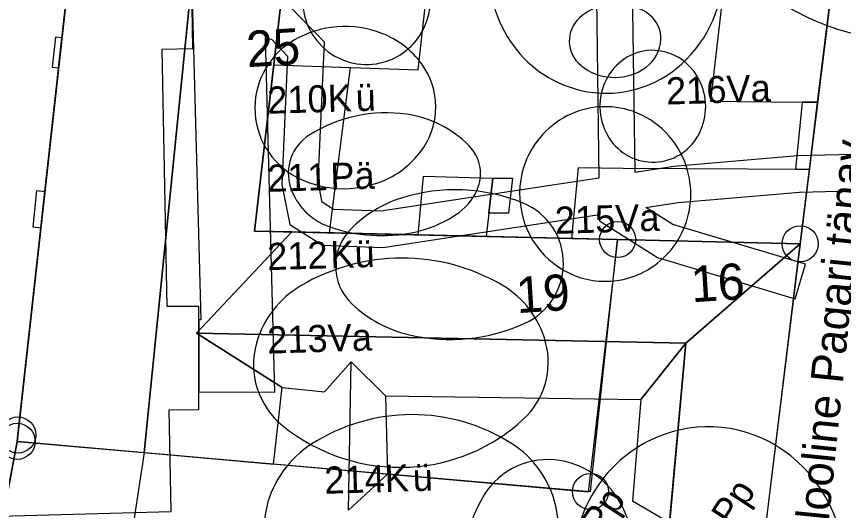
# Model space of a CAD drawing. Extents: x 738423 to 738903, y 6589762 to 6590172.
# Drawn here: x 738590.9 to 738636.72, y 6589894.31 to 6589921.66 of the extents above; entities that cross this region are included whole.
import ezdxf

# ---------------------------------------------------------------- set-up
doc = ezdxf.new("R2010")
doc.units = 0
for name, color, linetype in [('_1927_hoonestus', 7, 'Continuous'), ('_1927_katuse_kalded', 7, 'Continuous'), ('_1927_koordin_punktid_nr', 7, 'Continuous'), ('_1927_krundi_piir', 7, 'Continuous'), ('a_dendro_II_Vkl_puu', 7, 'Continuous'), ('a_dendro_III_vk_puu', 7, 'Continuous'), ('a_dendro_puu_nr', 7, 'Continuous'), ('a_dendro_V_vk_puu', 7, 'Continuous'), ('Default', 7, 'Continuous'), ('v_olol_hoone', 7, 'Continuous'), ('v_olol_kitsendus_tehnov', 7, 'Continuous'), ('v_vormistus_tekst', 7, 'Continuous')]:
    doc.layers.add(name, color=color, linetype=linetype)

# ---------------------------------------------------------------- blocks, each defined once
blk = doc.blocks.new('_U638')
at = {"layer": 'Default'}
for centre, radius, start, end in [((0.0017967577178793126, -0.006086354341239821), 0.016298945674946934, 62.43823725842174, 99.23130900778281), ((0.0017785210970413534, -0.00597414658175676), 0.01618526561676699, 99.23130900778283, 132.97828324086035), ((0.002383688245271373, -0.0049618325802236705), 0.015030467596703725, 24.06586474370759, 62.43823725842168), ((0.0009222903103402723, -0.005055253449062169), 0.014929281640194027, 132.97828324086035, 168.16056229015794), ((0.0028454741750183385, -0.004755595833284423), 0.014524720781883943, 325.34619089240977, 24.065864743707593), ((0.00048369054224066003, -0.004963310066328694), 0.0144811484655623, 168.16056229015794, 220.24997545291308), ((0.0015713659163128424, -0.003874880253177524), 0.016073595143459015, 269.78694623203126, 325.3461908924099), ((0.0015707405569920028, -0.004043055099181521), 0.01590541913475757, 220.24997545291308, 269.78694623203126)]:
    blk.add_arc(centre, radius, start, end, dxfattribs=at)
blk = doc.blocks.new('_U639')
at = {"layer": 'Default'}
for centre, radius, start, end in [((0.004641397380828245, -0.004188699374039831), 0.015204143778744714, 62.43823725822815, 111.04298782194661), ((0.003648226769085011, -0.001607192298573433), 0.01243817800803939, 111.04298782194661, 149.17299109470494), ((0.007830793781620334, 0.0019219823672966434), 0.008311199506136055, 354.7908139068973, 62.43823725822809), ((-0.0005217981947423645, 0.0008813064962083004), 0.007582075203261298, 149.1729910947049, 198.6357057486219), ((0.006724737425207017, 0.002022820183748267), 0.00942184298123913, 300.55754800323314, 354.7908139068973), ((0.0002487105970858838, 0.0011411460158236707), 0.008395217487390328, 198.63570574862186, 232.2443045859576), ((0.00306019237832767, 0.004771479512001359), 0.012986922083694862, 232.24430458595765, 259.1261887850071), ((0.0035614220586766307, 0.0073807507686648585), 0.015643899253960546, 259.1261887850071, 300.55754800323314)]:
    blk.add_arc(centre, radius, start, end, dxfattribs=at)
blk = doc.blocks.new('_U663')
at = {"layer": 'Default'}
for centre, radius, start, end in [((-0.003179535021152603, 0.002431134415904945), 0.009817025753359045, 76.98183598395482, 142.21769029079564), ((-0.00313893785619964, 0.0026067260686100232), 0.009636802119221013, 31.52910290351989, 76.98183598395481), ((-0.003567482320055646, 0.0027318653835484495), 0.009326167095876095, 142.2176902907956, 209.36902830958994), ((-0.0028356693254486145, 0.002792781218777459), 0.009281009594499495, 345.1635002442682, 31.529102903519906), ((-0.002983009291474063, 0.0028318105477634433), 0.009433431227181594, 318.45014178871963, 345.16350024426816), ((-0.0033842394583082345, 0.0028349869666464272), 0.009536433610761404, 209.36902830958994, 251.16622797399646), ((-0.003225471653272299, 0.00304669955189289), 0.00975741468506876, 292.19208800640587, 318.4501417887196), ((-0.0032726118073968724, 0.003162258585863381), 0.00988221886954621, 251.1662279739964, 292.1920880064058)]:
    blk.add_arc(centre, radius, start, end, dxfattribs=at)
blk = doc.blocks.new('_U672')
at = {"layer": 'Default'}
for centre, radius, start, end in [((-0.002101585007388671, 0.008719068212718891), 0.013254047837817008, 88.3470711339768, 146.6623908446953), ((-0.0021311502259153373, 0.007694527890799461), 0.014279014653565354, 39.22630250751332, 88.34707113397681), ((-0.01341153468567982, -0.0015141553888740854), 0.028840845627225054, 5.215032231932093, 39.22630250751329), ((0.010393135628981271, 0.000499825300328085), 0.02820978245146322, 146.6623908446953, 185.68101847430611), ((-0.013432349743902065, -0.0015160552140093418), 0.028861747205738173, 330.3262965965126, 5.215032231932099), ((0.010167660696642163, 0.0004773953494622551), 0.027983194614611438, 185.68101847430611, 223.49376727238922), ((-0.0006298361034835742, -0.008810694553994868), 0.014126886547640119, 279.58281790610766, 330.3262965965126), ((-0.0004907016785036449, -0.009634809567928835), 0.013291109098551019, 223.49376727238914, 279.5828179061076)]:
    blk.add_arc(centre, radius, start, end, dxfattribs=at)
blk = doc.blocks.new('_U666')
at = {"layer": 'Default'}
for centre, radius, start, end in [((0.00011899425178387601, -0.004345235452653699), 0.014377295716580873, 93.73643240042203, 132.97828326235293), ((0.00011601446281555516, -0.004299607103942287), 0.014331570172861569, 56.96948487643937, 93.73643240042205), ((0.0009683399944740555, -0.0029886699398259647), 0.012767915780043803, 17.930281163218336, 56.96948487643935), ((-0.0009846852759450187, -0.0031607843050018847), 0.012758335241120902, 132.9782832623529, 174.74476914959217), ((0.001317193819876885, -0.002875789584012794), 0.01240125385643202, 324.8404425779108, 17.930281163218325), ((-0.0013245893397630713, -0.0031295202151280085), 0.012416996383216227, 174.74476914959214, 226.8513130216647), ((-0.00011934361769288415, -0.0018639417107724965), 0.014158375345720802, 275.39216212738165, 324.8404425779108), ((-0.00012107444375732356, -0.001845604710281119), 0.014176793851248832, 226.85131302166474, 275.39216212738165)]:
    blk.add_arc(centre, radius, start, end, dxfattribs=at)
blk = doc.blocks.new('_U657')
at = {"layer": 'Default'}
for centre, radius, start, end in [((-0.00097990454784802, 0.0007999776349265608), 0.0072139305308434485, 87.51961632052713, 143.60493032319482), ((-0.000978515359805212, 0.0008320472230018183), 0.007181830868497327, 41.86952183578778, 87.51961632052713), ((-0.0008423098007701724, 0.0009541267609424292), 0.006998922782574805, 355.5925672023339, 41.869521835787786), ((-0.0011456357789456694, 0.00092214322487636), 0.007008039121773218, 143.60493032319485, 200.58225243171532), ((-0.0008819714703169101, 0.0009571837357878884), 0.00703870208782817, 318.4501417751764, 355.5925672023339), ((-0.00109799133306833, 0.0009400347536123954), 0.00705893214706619, 200.58225243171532, 241.43290441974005), ((-0.0010109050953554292, 0.001071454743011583), 0.007210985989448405, 281.7701057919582, 318.45014177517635), ((-0.001015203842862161, 0.0010920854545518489), 0.007232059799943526, 241.43290441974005, 281.7701057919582)]:
    blk.add_arc(centre, radius, start, end, dxfattribs=at)
blk = doc.blocks.new('_U658')
at = {"layer": 'Default'}
for centre, radius, start, end in [((-0.0005203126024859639, 0.00536265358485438), 0.008648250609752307, 93.96541354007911, 157.01522297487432), ((-0.0005176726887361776, 0.005324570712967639), 0.008686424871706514, 34.565999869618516, 93.96541354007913), ((-0.0026390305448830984, 0.0038630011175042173), 0.011262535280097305, 342.9805300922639, 34.56599986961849), ((0.0018660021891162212, 0.004350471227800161), 0.011240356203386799, 157.01522297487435, 211.61333323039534), ((-0.001366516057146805, 0.003473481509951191), 0.00993173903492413, 310.51471278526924, 342.9805300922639), ((0.0006726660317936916, 0.0036159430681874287), 0.009839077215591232, 211.61333323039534, 241.43290441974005), ((-0.00015588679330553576, 0.0020567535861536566), 0.008068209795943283, 274.37814596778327, 310.51471278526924), ((-0.00015839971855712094, 0.002089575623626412), 0.00810112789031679, 241.43290441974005, 274.3781459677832)]:
    blk.add_arc(centre, radius, start, end, dxfattribs=at)
blk = doc.blocks.new('_U659')
at = {"layer": 'Default'}
for centre, radius, start, end in [((0.0009135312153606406, 0.00814367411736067), 0.004993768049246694, 36.62143331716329, 112.83763452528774), ((0.001661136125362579, 0.006368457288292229), 0.006919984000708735, 112.83763452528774, 164.55428182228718), ((-0.007871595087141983, 0.0016141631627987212), 0.01593967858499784, 356.20504232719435, 36.621433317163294), ((0.011662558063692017, 0.0036050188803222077), 0.017296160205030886, 164.55428182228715, 196.5825048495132), ((-0.0041094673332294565, 0.0013646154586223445), 0.012169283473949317, 319.00795881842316, 356.2050423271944), ((0.007916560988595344, 0.0024895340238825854), 0.013387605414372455, 196.58250484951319, 219.71382654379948), ((0.0021317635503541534, -0.0023154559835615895), 0.005867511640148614, 219.71382654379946, 254.9708225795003), ((0.0017521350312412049, -0.003729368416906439), 0.004403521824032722, 254.97082257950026, 319.00795881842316)]:
    blk.add_arc(centre, radius, start, end, dxfattribs=at)
blk = doc.blocks.new('_U660')
at = {"layer": 'Default'}
for centre, radius, start, end in [((-0.00030942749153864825, 0.0014836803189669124), 0.0057334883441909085, 92.98118928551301, 140.95122577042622), ((-0.00030208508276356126, 0.0013426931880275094), 0.005874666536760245, 49.82920833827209, 92.98118928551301), ((-0.005270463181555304, -0.004542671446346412), 0.01357676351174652, 21.832289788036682, 49.829208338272), ((0.0060420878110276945, -0.003668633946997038), 0.013912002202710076, 140.95122577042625, 171.20520964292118), ((-0.011089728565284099, -0.006874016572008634), 0.019845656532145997, 342.07583257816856, 21.832289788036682), ((0.011936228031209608, -0.004580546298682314), 0.019876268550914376, 171.20520964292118, 208.92018104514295), ((0.0009415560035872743, -0.010765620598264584), 0.007200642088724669, 273.34239310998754, 342.0758325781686), ((0.00093529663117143, -0.010658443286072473), 0.007308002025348, 208.92018104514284, 273.3423931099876)]:
    blk.add_arc(centre, radius, start, end, dxfattribs=at)
blk = doc.blocks.new('_U661')
at = {"layer": 'Default'}
for centre, radius, start, end in [((-0.0030160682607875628, 0.007454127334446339), 0.008707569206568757, 78.4230499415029, 145.35801600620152), ((-0.003436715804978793, 0.005400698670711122), 0.010803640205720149, 34.65429433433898, 78.42304994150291), ((0.0068739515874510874, 0.000620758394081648), 0.02072869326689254, 145.35801600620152, 187.24173786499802), ((-0.012848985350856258, -0.001105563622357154), 0.022245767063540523, 4.5434303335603, 34.654294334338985), ((-0.01248887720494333, -0.001076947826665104), 0.021884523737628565, 333.96819896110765, 4.543430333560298), ((0.0062093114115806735, 0.0005363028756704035), 0.02005870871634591, 187.24173786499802, 226.85131301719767), ((-0.0021906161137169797, -0.00610682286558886), 0.010423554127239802, 289.0476065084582, 333.9681989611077), ((-0.0016057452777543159, -0.007800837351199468), 0.008631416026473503, 226.85131301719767, 289.0476065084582)]:
    blk.add_arc(centre, radius, start, end, dxfattribs=at)
blk = doc.blocks.new('_U662')
at = {"layer": 'Default'}
for centre, radius, start, end in [((-0.0028954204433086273, 0.006266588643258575), 0.009853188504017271, 80.49660816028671, 143.76371603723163), ((-0.0031717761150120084, 0.004615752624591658), 0.011526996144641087, 36.73116785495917, 80.49660816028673), ((0.0050267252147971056, 0.00046074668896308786), 0.019675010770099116, 143.76371603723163, 187.3383291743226), ((-0.0105701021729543, -0.0009050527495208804), 0.020758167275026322, 4.4809080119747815, 36.731167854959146), ((-0.010286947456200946, -0.0008828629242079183), 0.020474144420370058, 331.8756544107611, 4.48090801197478), ((0.00450953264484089, 0.0003941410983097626), 0.01915354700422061, 187.3383291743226, 228.46175316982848), ((-0.0021317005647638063, -0.0052418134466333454), 0.011227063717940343, 287.32246647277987, 331.8756544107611), ((-0.00170251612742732, -0.006617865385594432), 0.00978563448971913, 228.46175316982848, 287.32246647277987)]:
    blk.add_arc(centre, radius, start, end, dxfattribs=at)
blk = doc.blocks.new('_U665')
at = {"layer": 'Default'}
for centre, radius, start, end in [((-0.0029044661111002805, 0.0034915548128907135), 0.0034719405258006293, 46.56687312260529, 144.94764569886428), ((-0.004520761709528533, 0.0017843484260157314), 0.005822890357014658, 15.60075044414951, 46.56687312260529), ((-0.0008804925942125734, 0.0020715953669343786), 0.005944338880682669, 144.94764569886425, 215.63059108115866), ((-0.005270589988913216, 0.0015749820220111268), 0.00660139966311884, 346.56064947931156, 15.600750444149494), ((-0.004259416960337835, 0.0013333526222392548), 0.005561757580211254, 334.10172837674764, 346.56064947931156), ((-0.002239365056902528, 0.0010976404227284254), 0.004272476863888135, 215.63059108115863, 264.0891552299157), ((-0.003230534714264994, 0.0008337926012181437), 0.0044180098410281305, 320.11565064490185, 334.1017283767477), ((-0.002343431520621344, 9.247083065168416e-05), 0.0032619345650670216, 264.0891552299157, 320.11565064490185)]:
    blk.add_arc(centre, radius, start, end, dxfattribs=at)
blk = doc.blocks.new('_U664')
at = {"layer": 'Default'}
for centre, radius, start, end in [((-0.002498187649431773, -0.001611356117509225), 0.006568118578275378, 71.48372982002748, 126.93625442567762), ((-0.0023698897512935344, -0.001228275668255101), 0.006164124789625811, 41.982806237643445, 71.48372982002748), ((-0.0029878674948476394, -0.0009600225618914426), 0.005753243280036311, 126.93625442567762, 186.55361178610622), ((-0.0019370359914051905, -0.000838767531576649), 0.00558181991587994, 10.944438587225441, 41.98280623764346), ((-0.0018959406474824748, -0.0008308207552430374), 0.005539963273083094, 333.5917879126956, 10.944438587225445), ((-0.0030131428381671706, -0.000962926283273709), 0.0057278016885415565, 186.55361178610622, 244.4976123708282), ((-0.0024694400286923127, -0.0005460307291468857), 0.006180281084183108, 298.2944372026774, 333.5917879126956), ((-0.002652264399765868, -0.00020641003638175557), 0.006565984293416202, 244.49761237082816, 298.2944372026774)]:
    blk.add_arc(centre, radius, start, end, dxfattribs=at)

msp = doc.modelspace()

# ---------------------------------------------------------------- linework, layer by layer
at = {"layer": '_1927_hoonestus'}
for points in [[(738609.1419593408, 6589929.940140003), (738609.3368931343, 6589926.165239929), (738613.9533353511, 6589925.894244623), (738613.8912678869, 6589925.340685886), (738630.1483324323, 6589923.879602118), (738629.3435517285, 6589916.969136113), (738634.4211056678, 6589916.921415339), (738635.2838401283, 6589916.916987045), (738636.509191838, 6589926.891104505), (738627.5826462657, 6589928.059372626)], [(738605.5600914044, 6589922.532058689), (738605.1579677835, 6589918.9937799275), (738613.1474290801, 6589918.706638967), (738613.9533353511, 6589925.894244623), (738609.3368931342, 6589926.165239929), (738609.5082813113, 6589922.846301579), (738609.4744244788, 6589922.466374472)], [(738624.207189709, 6589909.313105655), (738622.5673353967, 6589895.324185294), (738590.9372064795, 6589898.135166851), (738593.6684053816, 6589922.731606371), (738605.5601169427, 6589922.53205826), (738605.1579677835, 6589918.9937799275), (738604.086427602, 6589909.782829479)], [(738593.4183435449, 6589920.479617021), (738593.0697797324, 6589920.519923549), (738592.878654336, 6589918.867104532), (738593.2337913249, 6589918.817589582)], [(738605.1579677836, 6589918.993779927), (738609.3886004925, 6589918.841731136), (738608.2173795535, 6589909.686391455), (738604.086427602, 6589909.782829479)], [(738634.4211056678, 6589916.921415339), (738634.0644192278, 6589913.2038506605), (738634.8273207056, 6589913.201010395), (738635.2838401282, 6589916.916987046)], [(738624.5146997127, 6589913.239404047), (738622.0179979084, 6589913.28052499), (738621.6553719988, 6589909.373207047), (738624.2071897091, 6589909.313105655), (738634.3211426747, 6589909.080822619), (738634.8273207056, 6589913.201010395)], [(738613.1604795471, 6589909.570993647), (738613.4556048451, 6589912.813731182), (738617.2915386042, 6589912.7055791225), (738616.9236948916, 6589909.483140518)], [(738617.2915386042, 6589912.7055791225), (738618.3765855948, 6589912.7055791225), (738618.1604766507, 6589910.776867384), (738617.0710209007, 6589910.7737674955)], [(738592.470753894, 6589911.945880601), (738592.0056230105, 6589912.0154890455), (738591.8046353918, 6589910.017250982), (738592.2500806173, 6589909.958556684)], [(738598.7561479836, 6589884.064893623), (738598.7561479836, 6589884.064893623), (738600.1654182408, 6589891.510843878), (738617.1576277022, 6589889.916511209), (738616.9587005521, 6589887.781161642), (738616.9587005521, 6589887.781161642), (738621.4793553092, 6589887.4869466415), (738621.2187353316, 6589884.178665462), (738631.1763472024, 6589883.225550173), (738634.3211426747, 6589909.080822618), (738624.2071897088, 6589909.313105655), (738622.5673353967, 6589895.324185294), (738590.9372064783, 6589898.13516685), (738590.9372064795, 6589898.13516685), (738586.1827055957, 6589872.62061175), (738613.3249623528, 6589869.722398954), (738613.2710881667, 6589869.728151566), (738614.3523733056, 6589877.812429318), (738614.3523733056, 6589877.812429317), (738614.3523733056, 6589877.812429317), (738615.0233334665, 6589882.235576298)]]:
    msp.add_lwpolyline(points, close=True, dxfattribs=at)
at = {"layer": '_1927_katuse_kalded'}
for points in [[(738597.9667878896, 6589897.510445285), (738600.5094751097, 6589922.616810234), (738593.6684053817, 6589922.73160637), (738590.9372064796, 6589898.13516685)], [(738597.9667878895, 6589897.510445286), (738605.1457848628, 6589896.872445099), (738605.6113334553, 6589901.124186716), (738600.881980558, 6589904.118928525), (738606.1519035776, 6589909.734610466), (738606.1519035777, 6589909.734610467), (738604.0864276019, 6589909.782829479), (738605.5600914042, 6589922.532058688), (738600.5094751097, 6589922.616810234)], [(738600.881980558, 6589904.118928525), (738627.9783805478, 6589903.577252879), (738634.3211426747, 6589909.080822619), (738606.1519035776, 6589909.734610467), (738606.1519035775, 6589909.734610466)], [(738634.3211545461, 6589909.080822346), (738627.9783805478, 6589903.577252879), (738626.1975412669, 6589883.702107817), (738631.1763472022, 6589883.225550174)], [(738600.881980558, 6589904.118928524), (738605.6113334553, 6589901.124186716), (738607.9681583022, 6589900.872549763), (738609.4494050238, 6589902.544400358), (738611.3403582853, 6589900.651739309), (738625.4909918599, 6589900.462473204), (738627.9783805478, 6589903.577252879)], [(738627.9783805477, 6589903.57725288), (738625.4909918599, 6589900.462473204), (738625.0359812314, 6589894.845607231), (738627.0879609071, 6589893.639680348)], [(738609.4494050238, 6589902.544400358), (738611.3403582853, 6589900.651739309), (738611.4495059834, 6589896.312231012), (738609.3012505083, 6589894.327721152)], [(738589.9993202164, 6589893.102093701), (738590.9372064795, 6589898.13516685), (738597.9667878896, 6589897.510445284), (738597.1362287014, 6589892.057225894), (738595.5346271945, 6589892.346110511)]]:
    msp.add_lwpolyline(points, close=True, dxfattribs=at)
at = {"layer": '_1927_koordin_punktid_nr'}
for centre in [(738624.2071897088, 6589909.313105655), (738634.3211426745, 6589909.080822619), (738590.9372064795, 6589898.13516685), (738590.975352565, 6589898.488217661), (738622.701350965, 6589895.352627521)]:
    msp.add_circle(centre, 0.9999999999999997, dxfattribs=at)
at = {"layer": '_1927_krundi_piir'}
for points in [[(738586.182705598, 6589872.620611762), (738590.9372064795, 6589898.13516685), (738590.975352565, 6589898.488217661), (738593.7110525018, 6589923.115674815), (738595.6482555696, 6589940.609766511), (738608.5799562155, 6589940.823351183), (738620.342268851, 6589941.795771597), (738638.2396178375, 6589940.94571321)], [(738638.2396178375, 6589940.94571321), (738636.5091918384, 6589926.8911045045), (738634.3211426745, 6589909.080822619), (738629.2817413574, 6589868.018556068)], [(738590.9372064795, 6589898.13516685), (738622.701350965, 6589895.352627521), (738624.2071897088, 6589909.313105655), (738634.3211426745, 6589909.080822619)]]:
    msp.add_lwpolyline(points, dxfattribs=at)
at = {"layer": 'v_olol_hoone'}
msp.add_lwpolyline([(738588.6389999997, 6589893.962), (738599.4669999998, 6589894.244), (738599.3599151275, 6589899.873880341), (738600.996, 6589899.9049999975), (738601.01, 6589905.608999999), (738599.250746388, 6589905.613317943), (738598.9797844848, 6589919.858869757), (738600.6690000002, 6589919.891000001), (738600.5770000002, 6589925.68), (738598.8695780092, 6589925.652865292), (738598.69, 6589935.093999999), (738587.8449999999, 6589934.8719999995), (738588.023237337, 6589925.688511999), (738587.4179999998, 6589925.677), (738587.4650000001, 6589923.205999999), (738588.0711907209, 6589923.217765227), (738588.4110435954, 6589905.707209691), (738587.885, 6589905.696999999), (738587.9331245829, 6589903.217432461), (738588.4591681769, 6589903.227642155)], close=True, dxfattribs=at)
at = {"layer": 'v_olol_kitsendus_tehnov'}
for points in [[(738645.6658428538, 6589914.234000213), (738634.174176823, 6589913.940901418), (738627.3268535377, 6589913.349518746), (738625.1699327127, 6589913.022275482), (738624.9687574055, 6589927.174521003)], [(738622.9712425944, 6589926.985478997), (738623.1740351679, 6589912.719462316), (738611.0883753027, 6589910.885852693), (738608.4611773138, 6589910.985108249), (738607.8451155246, 6589911.375195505), (738607.6154498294, 6589912.517408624), (738607.9602275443, 6589920.243137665), (738606.0076396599, 6589922.258668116)], [(738600.6344575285, 6589922.633238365), (738601.1052047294, 6589904.87122915), (738601.0081895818, 6589904.871383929), (738601.000089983, 6589900.871391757), (738605.2127952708, 6589900.864670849), (738604.6934804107, 6589920.459211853), (738605.0223603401, 6589920.401331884), (738605.9237724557, 6589919.470862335), (738605.606550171, 6589912.3625913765), (738606.0528844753, 6589910.142804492), (738607.8468226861, 6589909.006891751), (738611.2016246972, 6589908.88014731), (738623.2027287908, 6589910.700928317), (738623.2077973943, 6589910.344363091), (738626.4214640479, 6589908.311475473), (738634.0420799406, 6589906.028461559), (738634.6160443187, 6589907.944333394), (738627.2585359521, 6589910.148524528), (738625.7696267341, 6589911.090372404), (738627.5631464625, 6589911.362481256), (738634.285823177, 6589911.94309858), (738645.8481571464, 6589912.237999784)]]:
    msp.add_lwpolyline(points, dxfattribs=at)

# ---------------------------------------------------------------- block references
at = {"layer": 'a_dendro_II_Vkl_puu', "xscale": 500.0000000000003, "yscale": 500.0000000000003, "rotation": 85.69234851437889}
msp.add_blockref('_U659', (738612.484, 6589912.226000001), dxfattribs=at)
at = {"layer": 'a_dendro_III_vk_puu', "xscale": 500.0000000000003, "yscale": 500.0000000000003, "rotation": 85.69234851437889}
for name, p in [('_U672', (738640.577, 6589929.188)), ('_U666', (738622.0625, 6589924.4025)), ('_U658', (738611.1270000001, 6589916.654999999)), ('_U664', (738625.7979999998, 6589918.001)), ('_U663', (738625.017, 6589913.34)), ('_U660', (738612.2000000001, 6589907.9350000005)), ('_U661', (738612.2159999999, 6589903.609999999)), ('_U662', (738612.7799999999, 6589894.540999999)), ('_U638', (738626.7529999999, 6589890.438999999)), ('_U639', (738621.0009999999, 6589888.994))]:
    msp.add_blockref(name, p, dxfattribs=at)
at = {"layer": 'a_dendro_V_vk_puu', "xscale": 500.0000000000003, "yscale": 500.0000000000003, "rotation": 85.69234851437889}
for name, p in [('_U657', (738610.7929999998, 6589923.048)), ('_U665', (738625.1120000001, 6589921.624))]:
    msp.add_blockref(name, p, dxfattribs=at)

# ---------------------------------------------------------------- texts
at = {"layer": '_1927_koordin_punktid_nr'}
for s, p in [('25', (738603.6963071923, 6589918.854393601)), ('16', (738628.3258882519, 6589905.837651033)), ('19', (738618.6408225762, 6589905.234959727))]:
    msp.add_text(s, height=1.9999999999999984, rotation=3.560863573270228, dxfattribs=at).set_placement(p)
at = {"layer": 'a_dendro_puu_nr'}
for s, height, rotation, p in [('216Va', 1.5, 1.7381147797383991, (738626.9114689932, 6589916.787206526)), ('210K', 1.5, 1.7381147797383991, (738604.8148203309, 6589916.275926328)), ('ü', 1.5, 1.7381147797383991, (738609.7064977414, 6589916.424364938)), ('211', 1.5, 1.7381147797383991, (738604.8148203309, 6589911.951483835)), ('Pä', 1.5, 1.7381147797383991, (738608.3094600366, 6589912.057529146)), ('215Va', 1.5, 1.7381147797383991, (738620.7488101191, 6589909.624865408)), ('212', 1.5, 1.7381147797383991, (738604.8148203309, 6589907.615215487)), ('Kü', 1.5, 1.7381147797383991, (738608.3094600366, 6589907.721260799)), ('213Va', 1.5, 1.7381147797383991, (738604.8147272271, 6589902.9942804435)), ('214K', 1.5, 1.7381147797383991, (738607.9786747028, 6589895.227672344)), ('ü', 1.5, 1.7381147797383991, (738612.8703521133, 6589895.376110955)), ('189Pp', 1.5000000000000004, 56.88665020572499, (738628.7303964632, 6589890.528860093)), ('190Pp', 1.5000000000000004, 56.88665020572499, (738621.5220221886, 6589890.065686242))]:
    msp.add_text(s, height=height, rotation=rotation, dxfattribs=at).set_placement(p)
at = {"layer": 'v_vormistus_tekst'}
for s, rotation, p in [('ajalooline Suur tänav', 84.01099920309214, (738588.8891757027, 6589907.796530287)), ('ajalooline Pagari tänav', 84.19514024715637, (738635.5819194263, 6589890.509699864))]:
    msp.add_text(s, height=1.7999999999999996, rotation=rotation, dxfattribs=at).set_placement(p)

doc.saveas('drawing.dxf')
